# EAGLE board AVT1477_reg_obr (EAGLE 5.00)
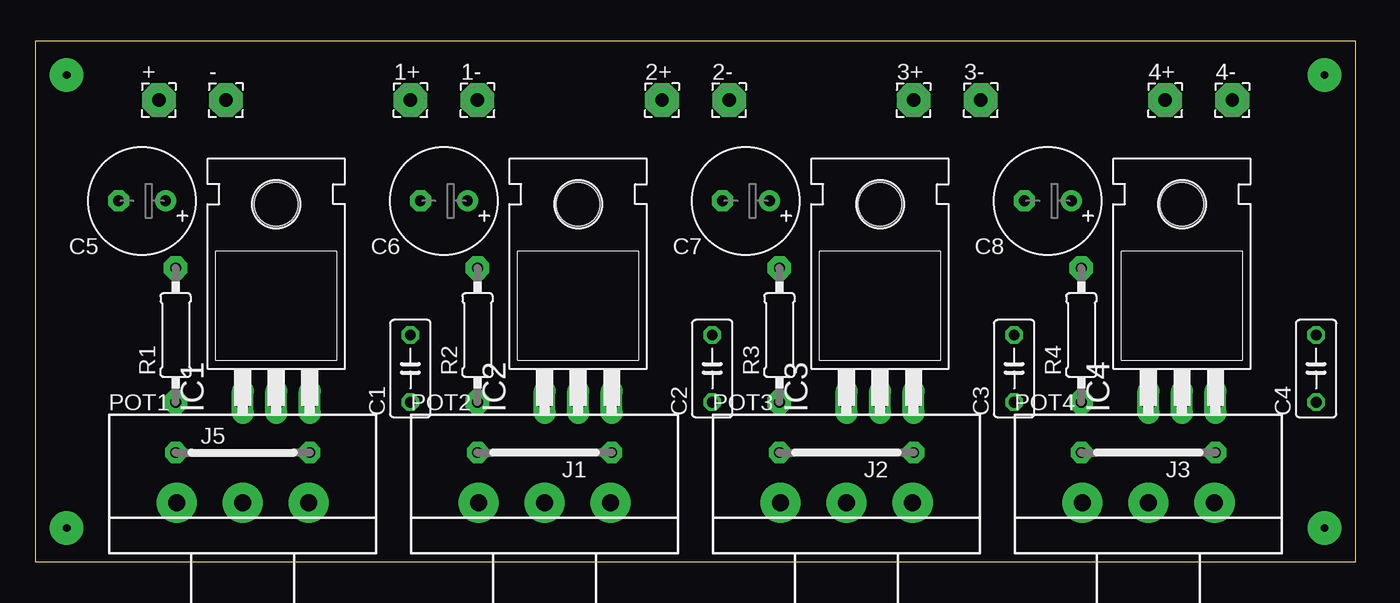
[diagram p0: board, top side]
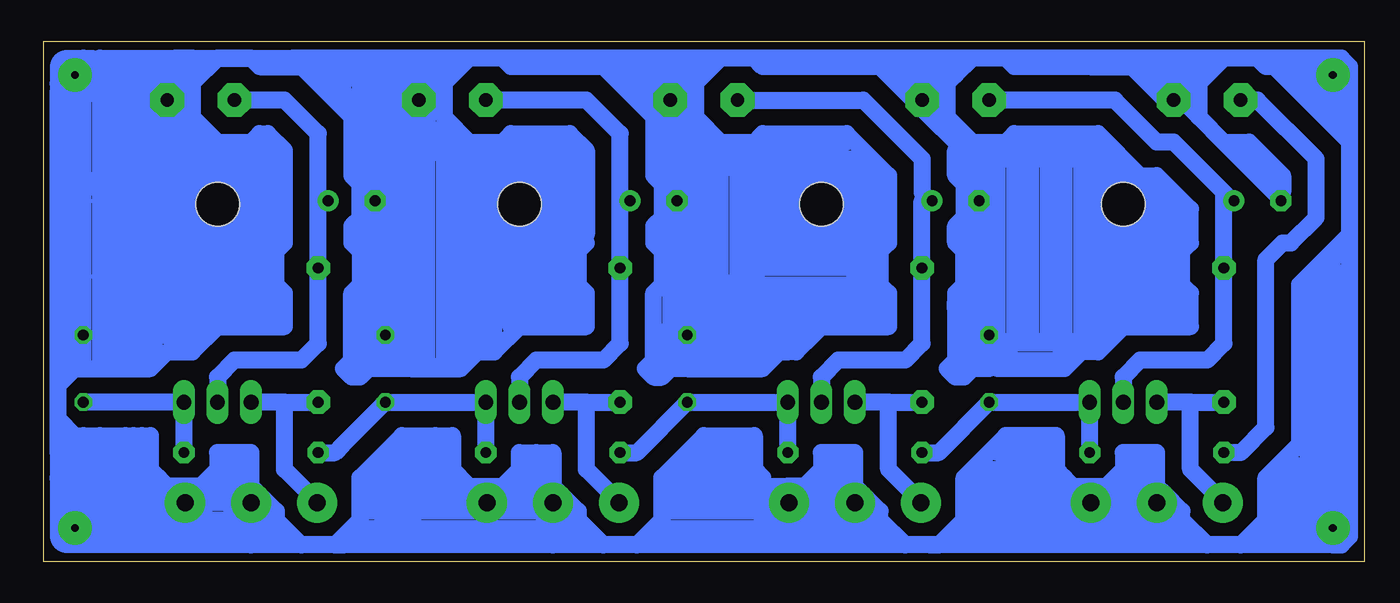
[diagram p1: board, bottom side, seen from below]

Size 100 x 39.36 mm. Coordinates in mm from the lower left corner, seen from the top.
Outline: 0,0 100,0 100,39.36 0,39.36 0,0
Copper layers (1*16): Top 0.035mm / dielectric 1.5mm / Bottom 0.035mm
Design rules "default": minimum track width 60mil, minimum drill 24mil, track to track 8mil, track to pad 8mil, pad to pad 8mil, via to via 8mil, smd to smd 8mil, copper to edge 40mil, drill to drill 8mil, minimum pad ring 10mil, minimum via ring 8mil, stop-mask expansion 4mil, vias tented up to drill 0mil, thermal gap 10mil

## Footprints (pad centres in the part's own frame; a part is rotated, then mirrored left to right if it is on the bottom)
2,54/1,0 = drill 1.016 pad 2.54 octagon: 1 0,0
C050-030X075 = drill 0.813 octagon: 1 -2.54,0; 2 2.54,0
E3,5-8 = drill 0.813 pad 1.6 round: + -1.778,0 | drill 0.813 pad 1.6 octagon: - 1.778,0
TO220H = drill 1.118 long: 1 -2.54,-10.16; 2 0,-10.16; 3 2.54,-10.16 | hole 3.302: 0,4.826
10 = drill 0.813 pad 1.6 octagon: 1 -5.08,0; 2 5.08,0
CIP20C-6MM = drill 1.3 pad 3.048 round: A -5,0; E 5,0; S 0,0
0207/10 = drill 0.813 pad 1.778 octagon: 1 -5.08,0; 2 5.08,0

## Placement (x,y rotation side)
1+  [2,54/1,0]  28.41,34.92 0 top
1-  [2,54/1,0]  33.49,34.92 0 top
2+  [2,54/1,0]  47.46,34.92 0 top
2-  [2,54/1,0]  52.54,34.92 0 top
3+  [2,54/1,0]  66.51,34.92 0 top
3-  [2,54/1,0]  71.59,34.92 0 top
4+  [2,54/1,0]  85.56,34.92 0 top
4-  [2,54/1,0]  90.64,34.92 0 top
+  [2,54/1,0]  9.36,34.92 0 top
-  [2,54/1,0]  14.44,34.92 0 top
C1  [C050-030X075]  28.41,14.6 90 top
C2  [C050-030X075]  51.27,14.6 90 top
C3  [C050-030X075]  74.13,14.6 90 top
C4  [C050-030X075]  96.99,14.6 90 top
C5  [E3,5-8]  8.09,27.3 180 top
C6  [E3,5-8]  30.95,27.3 180 top
C7  [E3,5-8]  53.81,27.3 180 top
C8  [E3,5-8]  76.67,27.3 180 top
IC1  317T  [TO220H]  18.25,22.22 0 top
IC2  317T  [TO220H]  41.11,22.22 0 top
IC3  317T  [TO220H]  63.97,22.22 0 top
IC4  317T  [TO220H]  86.83,22.22 0 top
J1  J10MM  [10]  38.57,8.25 180 top
J2  J10MM  [10]  61.43,8.25 180 top
J3  J10MM  [10]  84.29,8.25 180 top
J5  J10MM  [10]  15.71,8.25 0 top
POT1  [CIP20C-6MM]  15.71,4.44 0 top
POT2  [CIP20C-6MM]  38.57,4.44 0 top
POT3  [CIP20C-6MM]  61.43,4.44 0 top
POT4  [CIP20C-6MM]  84.29,4.44 0 top
R1  [0207/10]  10.63,17.14 90 top
R2  [0207/10]  33.49,17.14 90 top
R3  [0207/10]  56.35,17.14 90 top
R4  [0207/10]  79.21,17.14 90 top

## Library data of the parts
1+ 1- 2+ 2- 3+ 3- 4+ 4- + - = wirepad
C1-C8 R1-R4 = rcl
IC1-IC4 = linear
J1-J3 J5 = jumper
POT1-POT4 = pot

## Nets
N$1: 1+.1 C5.+ IC1.2 R1.2
N$2: C1.1 IC1.3 J1.2 J5.2
N$3: IC1.1 POT1.A R1.1
N$4: C2.1 IC2.3 J1.1 J2.2
N$5: 2+.1 C6.+ IC2.2 R2.2
N$6: C3.1 IC3.3 J2.1 J3.2
N$7: IC2.1 POT2.A R2.1
N$8: C4.1 IC4.3 J3.1
N$9: 3+.1 C7.+ IC3.2 R3.2
N$11: IC3.1 POT3.A R3.1
N$12: 4+.1 C8.+ IC4.2 R4.2
N$13: +.1 J5.1
N$14: IC4.1 POT4.A R4.1
N$20: 1-.1 2-.1 3-.1 4-.1 -.1 C1.2 C2.2 C3.2 C4.2 C5.- C6.- C7.- C8.- POT1.E POT2.E POT2.S POT3.E POT3.S POT4.E POT4.S

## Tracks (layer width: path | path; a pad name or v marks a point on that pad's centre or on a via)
N$1
  Bottom 1.27: IC1.2 18.25,13.96 16.98,15.23 11.9,15.23 10.63,16.5 R1.2 10.63,27.3 | 10.63,27.3 10,27.3 | 10,27.3 C5.+ | 1+.1 18.88,34.92 15.71,31.75 14.44,31.75 13.81,31.11 | 13.81,31.11 10.63,27.93 10.63,27.3 | 13.81,31.11 10,27.3
N$2
  Bottom 1.27: J1.2 32.22,8.25 C1.1 IC1.3 J5.2
N$3
  Bottom 1.27: 13.17,12.06 R1.1 | 13.17,12.06 IC1.1 | 13.17,12.06 13.17,6.98 10.63,4.44 POT1.A
N$4
  Bottom 1.27: J1.1 IC2.3 C2.1 55.08,8.25 J2.2
N$5
  Bottom 1.27: IC2.2 41.11,13.96 39.84,15.23 34.76,15.23 33.49,16.5 R2.2 33.49,27.3 32.85,27.3 | 2+.1 37.94,34.92 33.49,30.47 33.49,27.93 32.85,27.3 | 32.85,27.3 C6.+
N$6
  Bottom 1.27: J2.1 IC3.3 C3.1 77.3,8.89 77.94,8.25 J3.2
N$7
  Bottom 1.27: 36.03,12.06 R2.1 | 36.03,12.06 IC2.1 | 36.03,12.06 36.03,6.98 33.49,4.44 POT2.A
N$8
  Bottom 1.27: J3.1 IC4.3 C4.1
N$9
  Bottom 1.27: IC3.2 63.97,13.96 62.7,15.23 57.62,15.23 56.35,16.5 R3.2 56.35,27.3 | 56.35,27.3 C7.+ | 3+.1 58.89,34.92 56.35,32.38 56.35,27.3
N$11
  Bottom 1.27: 58.89,12.06 R3.1 | 58.89,12.06 IC3.1 | 58.89,12.06 58.89,6.98 56.43,4.52 POT3.A
N$12
  Bottom 1.27: IC4.2 86.83,13.96 85.56,15.23 80.48,15.23 79.21,16.5 R4.2 79.21,27.3 | C8.+ 79.21,27.3 | 79.21,27.3 79.21,32.38 81.75,34.92 4+.1 86.19,34.92
N$13
  Bottom 1.27: J5.1 9.36,8.25 7.46,10.16 7.46,22.86 6.18,24.12 5.55,24.12 3.64,26.03 3.64,30.47 8.09,34.92 +.1
N$14
  Bottom 1.27: 81.75,12.06 R4.1 | 81.75,12.06 IC4.1 | 81.75,12.06 81.75,6.98 79.21,4.44 POT4.A
N$16  (via drill 0.6 pad 2.54)
  other vias: 97.62,36.82
N$19
  Bottom 2.54: 71.59,1.9 74.77,1.9
N$20  (via drill 0.6 pad 2.54)
  Bottom 1.27: 79.84,37.46 83.66,37.46 84.29,38.09 | 60.16,18.41 60.16,31.75 70.95,31.75 | 83.02,3.17 88.1,3.17 88.73,2.54 86.19,2.54 86.19,3.17 POT4.S | 60.8,3.17 60.16,3.17 59.52,2.54 59.52,3.81 61.43,5.71 61.43,8.25 62.7,8.25 | 62.7,8.25 62.7,6.98 | 62.7,6.98 62.7,5.08 | 62.7,6.98 64.61,5.08 63.34,5.08 63.34,5.71 65.24,5.71 | 69.05,5.71 67.78,5.71 | 67.78,5.71 65.24,5.71 | 70.32,9.52 69.05,5.71 | 70.32,9.52 72.86,9.52 76.03,6.34 76.03,3.81 | 76.03,3.81 76.03,2.54 | 76.03,2.54 76.03,1.9 | 76.03,2.54 62.06,2.54 62.06,3.81 75.4,3.81 75.4,4.44 | 75.4,4.44 75.4,6.34 74.77,4.44 66.51,5.08 74.77,5.08 75.4,4.44 | 75.4,4.44 75.4,5.71 74.77,6.34 | 74.77,6.34 74.13,6.98 | 74.13,6.98 72.22,8.89 70.32,8.89 69.05,7.61 73.5,7.61 74.13,6.98 | 69.05,5.71 69.05,8.25 | 69.05,8.25 69.05,9.52 70.32,9.52 | 76.03,3.81 76.03,3.17 77.94,1.26 | 4.28,1.9 4.28,21.59 1.1,24.76 | 28.41,27.3 28.41,23.49 | 28.41,27.3 C6.- | 51.27,20.95 51.27,27.3 C7.- 52.03,34.41 2-.1 | 74.13,17.78 74.13,27.3 74.77,27.3 | 96.99,21.59 96.99,27.3 97.62,27.3 90.64,34.28 4-.1 90,35.55 90,38.09 88.73,38.09 | 96.99,21.59 C4.2 96.99,14.6 | C5.- 6.31,27.43 10.63,31.75 | 12.54,33.65 13.81,34.92 -.1 15.08,34.92 17.61,37.46 20.79,37.46 | 12.54,33.65 10.63,31.75 | 20.79,37.46 26.5,37.46 27.14,38.09 29.68,38.09 30.95,36.82 | 33.49,34.28 30.95,36.82 | 33.49,34.28 1-.1 | 30.31,31.11 33.49,34.28 | 28.41,29.21 28.41,27.3 | 37.3,38.09 46.19,38.09 | 46.19,38.09 49.37,38.09 | 49.37,38.09 2-.1 | 51.27,17.78 C2.2 51.27,15.87 | 51.27,18.41 51.27,17.78 | 51.27,19.68 51.27,18.41 | 51.27,30.47 51.27,20.95 | 51.27,31.75 51.27,33.02 53.17,34.92 | 53.17,34.92 53.81,35.55 | 53.81,35.55 56.35,38.09 56.98,38.09
  Bottom 1.27: 58.25,38.09 65.24,38.09 | 65.24,38.09 68.41,38.09 | 69.69,36.82 3-.1 71.59,30.47 74.77,27.3 | 74.77,27.3 C8.- | 74.13,17.78 C3.2 | 74.13,17.78 74.13,31.11 81.11,38.09 | 84.29,38.09 81.11,38.09 | 88.73,38.09 84.29,38.09 | 98.26,34.28 97.75,33.78 | 98.26,34.28 98.89,35.55 98.89,33.65 | 28.41,29.21 28.41,23.49 | 28.41,23.49 C1.2 | 37.3,38.09 36.66,37.46 | 36.66,37.46 30.31,31.11 | 29.04,29.84 28.41,29.21 | 8.09,38.09 1.74,38.09 1.1,37.46 1.1,31.75 | 8.09,38.09 37.3,38.09 | 1.1,24.12 1.1,1.9 1.74,1.26 2.38,1.26 | 2.38,1.26 9.36,1.26 | 9.36,1.26 32.85,1.26 | 32.85,1.26 34.76,1.26 | 61.43,1.26 61.43,3.17 | 34.76,1.26 55.08,1.26 | 55.08,1.26 61.43,1.26 | 61.43,1.26 77.94,1.26 | 77.94,1.26 77.3,1.26 | 77.94,1.26 84.29,1.26 84.92,1.9 88.1,1.9 | 11.27,37.46 20.79,37.46 | 11.27,37.46 10.63,38.09 8.09,38.09 | 8.09,38.09 7.46,37.46 6.82,37.46 | 6.18,37.46 1.74,37.46 1.74,33.65 1.1,33.02 1.1,24.76 | 2.38,1.26 3.01,1.9 3.64,1.9 3.64,21.59 1.1,24.12 | 2.38,33.02 v2.38,36.82 | 1.1,31.75 2.38,33.02 | 1.1,24.76 1.1,31.75 | 1.1,24.12 3.01,22.22 3.01,6.98 | 3.01,6.98 3.01,2.54 2.38,1.9 v2.38,2.54 | v2.38,2.54 2.38,3.81 | 2.38,3.81 2.38,22.22 | 2.38,3.81 3.64,2.54 3.64,6.34 3.01,6.98 | 2.38,1.26 v2.38,2.54 | v2.38,2.54 2.38,6.34 3.01,6.98 | 1.1,24.12 1.1,24.76 | 1.1,24.76 4.92,20.95 4.92,8.89 7.46,6.34 7.46,5.08 | 7.46,5.08 7.46,1.9 4.92,1.9 4.92,6.98 5.55,7.61 5.55,6.98 6.82,5.71 | 6.82,5.71 6.82,3.17 6.18,2.54 6.18,5.08 5.55,5.71 6.82,5.71 | 7.46,5.08 6.82,5.71 | 7.46,5.08 7.46,3.17 9.36,1.26 | 9.36,1.26 11.9,1.26 13.81,3.17 | 13.81,3.17 15.71,5.08 | 13.81,3.17 13.81,3.81 15.08,5.08 | 15.08,5.08 15.71,5.71 15.71,8.25 16.34,8.25 | 16.34,8.25 16.98,8.25 16.98,6.98 18.25,5.71 18.88,5.71
  Bottom 1.27: 22.06,5.71 24.6,8.25 | 24.6,8.25 23.33,9.52 | 23.33,9.52 27.14,9.52 29.68,6.98 | 30.31,3.17 30.31,1.9 13.81,1.9 15.08,3.17 | 30.31,3.17 18.25,3.17 | 18.25,3.17 15.08,3.17 | 30.31,3.17 30.31,4.44 | 30.31,4.44 30.31,5.71 | 15.71,5.08 15.08,5.08 | 15.71,5.08 16.34,5.71 16.98,5.71 | 30.31,5.71 22.06,5.71 | 16.98,5.71 18.88,5.71 | 18.88,5.71 19.52,5.71 | 30.31,5.71 30.31,6.34 29.68,6.98 | 29.68,6.98 23.96,6.98 | 23.96,6.98 23.33,6.98 22.7,6.34 23.96,6.98 | 23.96,6.98 23.96,8.25 24.6,8.25 | 24.6,8.25 27.77,8.25 | 16.98,5.71 16.34,6.34 | 32.85,1.26 32.22,1.26 30.31,3.17 | 34.76,1.26 36.66,3.17 | 36.66,3.17 37.94,4.44 37.94,1.9 36.66,1.9 37.3,2.54 | 36.66,3.17 36.66,3.81 38.57,5.71 38.57,8.25 | 38.57,8.25 39.84,8.25 39.84,6.98 | 39.84,6.98 39.84,5.08 | 39.84,6.98 41.11,5.71 42.38,5.71 | 46.19,6.34 46.19,9.52 50,9.52 53.17,6.34 53.17,3.17 | 46.19,6.98 47.46,7.61 | 46.19,6.34 44.92,5.08 44.28,5.08 | 46.19,5.71 43.65,5.71 | 43.65,5.71 43.02,5.08 42.38,5.08 | 42.38,5.08 40.48,5.08 40.48,4.44 39.2,3.17 44.92,3.17 44.92,1.9 39.84,1.9 39.2,2.54 43.02,2.54 44.6,4.12 | 44.6,4.12 44.92,4.44 46.19,6.34 | 46.19,6.34 47.46,7.61 | 47.46,7.61 46.19,5.71 | 53.17,3.17 53.17,2.54 | 53.17,2.54 53.17,1.9 | 53.17,2.54 45.55,2.54 45.55,6.34 46.19,6.98 | 46.19,6.98 46.19,6.34 | 46.19,6.34 46.19,5.71 | 46.19,5.71 46.19,3.81 52.54,3.81 52.54,5.08 | 52.54,5.08 52.54,5.71 49.37,8.89 46.82,8.89 46.82,5.08 52.54,5.08 | 52.54,5.08 51.91,5.08 48.73,8.25 48.09,8.25 48.09,6.34 47.46,5.71 50,5.71 48.73,6.98 | 55.08,1.26 53.17,3.17 | 55.08,1.26 57.62,1.26 61.43,5.08 | 61.43,3.17 POT3.S 61.43,5.08 | 61.43,3.17 61.43,2.54 60.8,1.9 60.16,1.9 | 60.16,1.9 59.52,1.9
  Bottom 1.27: 61.43,3.17 60.16,1.9 | 77.94,1.26 80.48,1.26 84.29,5.08 84.29,5.71 | 84.29,5.71 84.29,8.25 | 84.29,8.25 85.56,8.25 | POT4.S 85.56,1.9 83.02,1.9 82.39,2.54 82.39,3.81 84.29,5.71 | 85.56,8.25 POT4.S | 85.56,8.25 85.56,6.98 | 85.56,6.98 86.83,5.71 | 86.83,5.71 87.47,5.08 | 86.83,5.71 88.1,5.71 | 91.91,5.71 92.55,8.89 91.91,8.89 | 91.91,8.89 91.91,6.98 | 91.91,5.71 91.91,2.54 90,2.54 90,4.44 | 90,4.44 90,5.08 90.64,5.71 | 90.64,5.71 91.28,6.34 91.28,3.17 88.73,3.17 86.19,5.71 88.1,5.71 | 88.1,5.71 90.64,5.71 | 90.64,5.71 91.91,5.71 | 91.91,5.71 93.18,9.52 93.81,9.52 | 93.81,9.52 95.72,9.52 98.89,6.34 98.26,1.9 92.55,1.9 92.55,6.98 | 92.55,6.98 92.55,8.25 91.91,8.89 | 91.91,8.89 92.55,9.52 93.81,9.52 | 93.81,9.52 94.45,8.89 | 98.26,3.81 98.26,5.08 95.72,7.61 95.08,6.98 92.55,6.98 | 98.26,2.54 v97.62,2.54 93.81,2.54 93.18,3.17 93.18,8.89 94.45,8.89 | 94.45,8.89 95.72,8.89 98.26,6.34 | 98.26,6.34 98.26,4.44 97.62,3.81 | 97.62,3.81 96.99,3.17 94.45,3.17 93.81,3.81 93.81,6.98 94.45,7.61 93.81,8.25 93.81,7.61 97.62,3.81 | 97.62,3.81 95.08,3.81 94.45,4.44 94.45,5.08 | 94.45,5.08 94.45,5.71 | 94.45,5.08 95.08,4.44 95.08,5.08 95.72,5.08 96.36,4.44 97.62,4.44 97.62,5.08 95.72,6.98 | 91.91,6.98 91.91,9.52 93.81,9.52 | 91.91,6.98 91.91,5.71 | 2.38,33.02 6.82,37.46 | 6.82,37.46 6.18,37.46 | 6.18,37.46 3.64,37.46 3.01,36.82 3.01,34.92 4.92,36.82 | 6.18,37.46 4.92,37.46 3.64,36.19 | 11.27,37.46 12.54,36.19 | 12.54,36.19 12.54,33.65 | 12.54,36.19 13.17,36.82 15.08,36.82 | 15.08,36.82 15.71,36.82 | 15.08,36.82 13.81,35.55 13.17,36.19 15.08,36.19 | 10.63,31.75 8.73,31.75 6.18,29.21 6.18,27.93 9.36,31.11 | 30.95,36.82 31.58,36.82 31.58,33.02 32.85,34.28 32.22,34.28 29.68,31.75
  Bottom 1.27: 29.68,31.75 29.04,31.11 | 29.68,31.75 27.14,31.75 26.5,32.38 20.15,32.38 16.98,29.21 | 16.98,29.21 13.81,26.03 | 16.98,29.21 15.71,29.21 13.17,26.66 13.17,24.12 13.81,23.49 13.81,20.95 13.17,20.32 13.17,17.78 14.44,17.78 | 14.44,17.78 18.25,17.78 20.15,15.87 21.42,15.87 22.7,14.6 27.77,14.6 | 28.41,23.49 28.41,14.6 29.68,14.6 30.31,13.96 30.95,13.96 31.58,14.6 30.95,15.23 | 28.41,23.49 28.41,31.11 20.15,31.11 20.15,17.78 | 20.15,17.78 20.15,16.5 27.77,16.5 | 27.77,16.5 27.77,15.23 26.5,15.23 | 26.5,15.23 23.33,15.23 22.7,15.87 22.06,15.87 20.15,17.78 | 20.15,17.78 14.44,17.78 | 14.44,17.78 14.44,26.03 19.52,26.03 | 19.52,26.03 19.52,30.47 15.71,26.66 | 15.71,26.66 18.88,26.66 18.88,28.57 | 18.88,28.57 18.88,29.21 | 18.88,28.57 17.61,27.3 16.34,27.3 15.71,26.66 | 15.71,26.66 15.71,18.41 16.98,18.41 16.98,25.39 18.25,25.39 18.25,18.41 19.52,18.41 19.52,26.03 | 21.42,17.14 21.42,30.47 22.7,30.47 22.7,17.14 23.96,17.14 23.96,30.47 25.23,30.47 25.23,17.14 26.5,17.14 26.5,30.47 27.77,30.47 27.77,16.5 | 27.77,16.5 26.5,15.23 | 30.95,15.23 30.31,15.87 30.31,20.32 | 30.31,31.11 30.31,20.95 | 30.31,31.11 29.04,29.84 | 29.04,29.84 29.04,15.87 30.31,14.6 | 30.95,19.05 30.95,15.23 | 30.95,19.05 30.95,19.68 30.31,20.32 | 30.31,20.95 30.31,20.32 | 30.31,20.95 30.31,23.49 30.95,24.12 30.95,25.39 29.68,26.66 29.68,27.93 30.95,29.21 30.95,31.11 | 30.95,19.05 30.95,20.32 30.31,20.95 | 36.66,37.46 45.55,37.46 46.19,38.09 | 46.19,38.09 48.73,38.09 50.63,36.19 50.63,33.65 48.73,31.75 46.19,31.75 45.55,32.38 39.2,32.38 37.3,30.47 | 37.3,30.47 36.03,29.21 36.03,24.12 36.66,23.49 36.66,20.95 36.03,20.32 36.03,17.78 41.11,17.78 41.74,17.14
  Bottom 1.27: 41.74,17.14 43.02,15.87 43.65,15.87 | 43.65,15.87 44.28,15.87 45.55,14.6 51.27,14.6 | 51.27,15.87 51.27,14.6 | 51.27,15.87 43.65,15.87 | 43.65,17.14 43.65,15.87 | 43.65,17.14 50.63,17.14 | 41.74,17.14 43.65,17.14 | 41.74,17.14 41.74,18.41 51.27,18.41 | 51.27,18.41 36.66,18.41 36.66,19.68 51.27,19.68 | 51.27,20.95 51.27,19.68 | 51.27,20.95 38.57,20.95 | 38.57,20.95 37.3,20.95 37.3,30.47 | 51.27,30.47 37.3,30.47 | 51.27,31.75 51.27,30.47 | 51.27,31.75 50,31.75 | 50,31.75 39.2,31.75 | 50,31.75 50.63,32.38 50.63,34.28 51.27,34.92 | 51.27,34.92 51.27,35.55 | 51.27,30.47 51.27,34.92 | 51.27,30.47 50.63,30.47 50,29.84 50,21.59 48.73,21.59 48.73,29.84 47.46,29.84 47.46,21.59 46.19,21.59 46.19,29.84 38.57,29.84 38.57,22.22 | 38.57,22.22 38.57,21.59 37.94,21.59 | 37.94,21.59 36.66,20.32 37.94,20.32 38.57,20.95 | 37.94,21.59 38.57,22.22 | 38.57,22.22 45.55,22.22 45.55,29.21 39.2,29.21 39.2,23.49 | 39.2,23.49 39.2,22.86 | 39.2,23.49 44.92,23.49 44.92,28.57 40.48,28.57 40.48,24.12 43.65,24.12 43.65,27.93 42.38,27.93 41.74,27.3 | 41.74,27.3 41.74,26.03 41.11,25.39 41.74,25.39 42.38,24.76 42.38,26.66 43.02,27.3 41.74,27.3 | 41.74,27.3 41.11,27.93 | 51.27,14.6 52.54,14.6 53.17,13.96 53.81,13.96 54.45,14.6 53.81,15.23 | 51.27,17.78 53.81,15.23 | 51.27,17.78 51.27,16.5 53.17,14.6 | 53.81,15.23 53.17,15.23 | 53.81,15.23 53.81,20.32 53.17,20.95 | 53.17,20.95 52.54,21.59 | 53.17,20.95 53.17,23.49 53.81,24.12 53.81,25.39 53.17,26.03 | 53.17,26.03 52.54,26.66 52.54,26.03 53.17,26.03 | 53.17,26.03 53.17,28.57 53.81,29.21 53.81,34.28 53.17,34.92 | 2-.1 53.17,34.92 | 2-.1 52.54,17.78 53.17,17.14 | 57.62,37.46 53.17,33.02
  Bottom 1.27: 58.25,38.09 57.62,37.46 | 56.98,38.09 58.25,38.09 | 49.37,38.09 56.98,38.09 | 49.37,38.09 51.27,38.09 53.17,36.19 | 53.17,36.19 55.08,36.19 | 55.08,36.19 56.35,37.46 51.91,37.46 | 51.91,37.46 51.27,37.46 | 53.17,36.19 51.91,37.46 | 53.81,35.55 52.54,35.55 51.27,36.82 | 56.98,38.09 57.62,37.46 | 57.62,37.46 64.61,37.46 65.24,38.09 | 65.24,38.09 67.78,38.09 70.95,34.92 70.95,35.55 69.69,36.82 | 68.41,38.09 69.69,36.82 | 69.69,36.82 69.69,33.65 67.78,31.75 65.24,31.75 64.61,32.38 60.16,32.38 58.89,31.11 58.89,24.76 59.52,24.12 59.52,23.49 | 59.52,23.49 59.52,20.95 58.89,20.32 58.89,17.78 62.7,17.78 | 63.97,17.78 62.7,17.78 | 63.97,17.78 65.88,15.87 67.14,15.87 | 67.14,15.87 68.41,14.6 70.95,14.6 | 72.22,14.6 73.5,14.6 | 73.5,14.6 74.13,14.6 74.13,17.78 | 59.52,23.49 58.89,24.12 | 70.95,14.6 70.95,30.47 | 72.22,14.6 70.95,14.6 | 72.22,38.09 72.22,14.6 | 68.41,38.09 72.22,38.09 | 68.41,38.09 69.69,38.09 71.59,36.19 71.59,36.82 | 71.59,36.82 71.59,37.46 | 71.59,36.82 70.95,36.19 70.95,30.47 | 70.95,30.47 70.95,31.75 | 70.95,31.75 69.69,33.02 69.69,15.23 68.41,15.23 68.41,31.11 61.43,31.11 61.43,18.41 | 53.17,32.38 53.17,34.28 55.08,36.19 | 62.7,17.78 62.7,30.47 67.14,30.47 67.14,15.87 | 67.14,15.87 66.51,15.87 65.88,16.5 65.88,29.84 64.61,29.84 64.61,17.78 63.97,17.78 | 63.97,17.78 63.97,29.84 | 73.5,38.09 73.5,14.6 | 72.22,38.09 73.5,38.09 | 73.5,14.6 72.86,15.23 | 73.5,14.6 75.4,14.6 76.03,13.96 76.67,13.96 77.3,14.6 76.67,15.23 | 76.67,15.23 76.03,15.87 76.03,26.03 | 76.03,34.28 76.03,26.03 | 76.03,38.09 76.03,34.28 | 74.77,38.09 76.03,38.09 | 73.5,38.09 74.77,38.09 | 74.77,38.09 74.77,16.5 76.03,15.23 | 76.67,15.23 76.67,20.32 75.4,21.59 75.4,22.86 76.67,24.12 76.67,25.39 76.03,26.03
  Bottom 1.27: 76.03,26.03 76.03,28.57 76.67,29.21 76.67,33.65 81.11,38.09 | 76.03,38.09 81.11,38.09 | 76.03,38.09 76.03,35.55 76.67,34.92 79.21,37.46 76.67,37.46 76.67,36.82 77.3,36.19 77.3,35.55 76.03,34.28 | 84.29,38.09 86.83,38.09 88.73,36.19 88.73,34.92 | 88.73,34.92 88.73,33.02 | 88.73,34.92 88.73,33.65 86.83,31.75 84.29,31.75 83.66,32.38 83.02,32.38 81.75,31.11 81.75,24.12 82.39,23.49 82.39,20.95 81.75,20.32 81.75,17.78 86.83,17.78 88.73,15.87 90.64,15.87 91.91,14.6 95.72,14.6 | 96.99,14.6 95.72,14.6 | 95.72,38.09 95.72,14.6 | 95.72,38.09 88.73,38.09 | 88.73,38.09 88.73,37.46 95.08,37.46 95.08,17.14 | 95.08,15.87 94.45,15.23 91.91,15.23 91.28,15.87 95.08,15.87 | 95.08,17.14 95.08,15.87 | 95.08,17.14 91.91,17.14 | 90.64,17.14 88.1,17.14 87.47,17.78 88.73,17.78 | 93.18,17.78 94.45,17.78 94.45,36.82 93.18,36.82 | 91.91,36.82 93.18,36.82 | 90.64,36.82 88.73,36.82 88.73,17.78 | 88.73,17.78 90,17.78 | 90,17.78 90,36.19 90.64,36.82 | 91.28,36.82 90.64,36.82 | 91.91,36.82 91.28,36.82 | 91.91,17.14 91.91,36.82 | 91.91,17.14 90.64,17.14 | 90.64,17.14 90.64,36.19 91.28,36.82 | 93.18,36.82 91.28,36.82 | 93.18,36.82 93.18,17.78 | 93.18,17.78 90,17.78 | 90,17.78 89.37,18.41 87.47,18.41 | 83.66,18.41 83.02,18.41 82.39,19.05 82.39,31.11 88.73,31.11 89.37,30.47 89.37,31.75 87.47,31.75 87.47,18.41 | 87.47,18.41 83.66,18.41 | 83.66,18.41 83.66,30.47 86.83,30.47 86.83,19.05 85.56,19.05 | 85.56,19.05 84.29,19.05 84.29,29.21 84.92,29.84 85.56,29.84 85.56,19.05 | 96.99,21.59 96.99,34.92 | 96.99,34.92 96.99,38.09 96.36,37.46 | 96.36,37.46 95.72,38.09 | 98.26,14.6 97.62,14.6 | 97.62,14.6 96.99,14.6 | 98.89,15.23 98.26,14.6
  Bottom 1.27: 98.89,15.23 98.89,14.6 | 98.89,15.23 98.89,26.03 | 98.89,26.03 98.26,26.66 | 98.89,33.65 98.89,34.28 98.26,34.28 | 98.26,34.28 98.26,15.87 | 98.26,14.6 98.89,14.6 | 98.26,14.6 97.62,15.23 98.26,15.23 | 96.99,34.92 97.62,34.92 98.89,36.19 97.62,36.19 | 98.89,26.03 98.89,33.65 | 96.36,37.46 97.62,37.46 | 16.34,8.25 18.25,8.25 18.25,6.98 19.52,5.71 | 22.06,5.71 19.52,5.71 | 23.33,9.52 23.33,6.34 | 38.57,8.25 41.11,8.25 41.11,6.98 42.38,5.71 | 42.38,5.71 43.65,5.71 | 62.7,8.25 63.97,8.25 63.97,6.98 65.24,5.71 | 74.77,5.71 70.32,5.71 69.69,6.34 74.77,6.34 | 74.77,6.34 70.95,6.34 69.05,8.25 | 69.05,8.25 69.05,6.98 67.78,5.71 | 84.29,8.25 86.83,8.25 86.83,6.98 88.1,5.71 | 90.64,5.71 91.91,6.98 | POT1.E 20.15,4.44 18.88,5.71 | 16.34,4.44 15.08,3.17 | 30.31,4.44 16.34,4.44 | 16.34,4.44 16.98,4.44 18.25,3.17 | POT2.E 43.02,4.44 42.38,5.08 | 44.6,4.12 44.28,4.44 POT2.S | POT4.S 85.56,4.44 | 85.56,4.44 POT4.E 90,4.44 | POT3.E 65.88,4.44 65.24,5.08 61.43,5.08 | 85.56,6.98 85.56,4.44 | 98.89,14.6 98.26,15.23 | 98.89,9.52 98.89,10.79 | 98.89,10.79 98.89,14.6 | 98.89,9.52 98.89,8.89 98.26,8.25 | 98.89,9.52 98.26,8.89 98.26,6.98 98.26,6.34 | 98.89,15.23 98.26,15.23 | 98.89,8.25 98.89,15.23 | 98.26,6.34 98.26,7.61 | 98.26,8.25 98.26,6.34 | 98.26,8.25 98.89,8.25 | 98.89,8.25 98.89,9.52 | 96.99,9.52 97.62,9.52 98.89,10.79 | 98.89,10.79 98.89,13.33 97.62,14.6
  Bottom 2.54: 98.26,1.9 88.73,1.9 | 88.73,1.9 86.83,1.9 | 98.26,2.54 98.26,8.25 | 98.26,36.82 98.26,37.46 96.36,37.46 98.26,36.82 | 98.26,36.82 98.26,15.23 98.26,16.5 | 98.26,2.54 v97.62,2.54 96.99,2.54 94.45,5.08 94.45,8.89 | 98.26,8.25 98.26,7.61 95.72,7.61 94.45,8.89 | 98.26,8.25 98.26,8.89 94.45,8.89 | 98.26,2.54 98.26,3.81 | 88.1,1.9 98.26,1.9 | 98.26,1.9 98.26,2.54 | 98.26,2.54 98.26,5.71 | 98.26,5.71 98.26,6.34 | 98.26,36.82 98.26,31.75 | 98.26,36.82 98.26,29.21 | 98.26,5.71 98.26,6.98 | 88.73,1.9 82.39,1.9
N$21
  Bottom 1.27: 39.2,6.98 39.2,2.54 38.57,1.9
N$22
  Bottom 1.27: 76.03,14.6 74.77,15.87
N$25
  Bottom 1.27: 31.58,37.46 35.39,37.46 35.39,36.82 34.12,35.55 33.49,35.55 32.22,36.82 34.12,36.82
